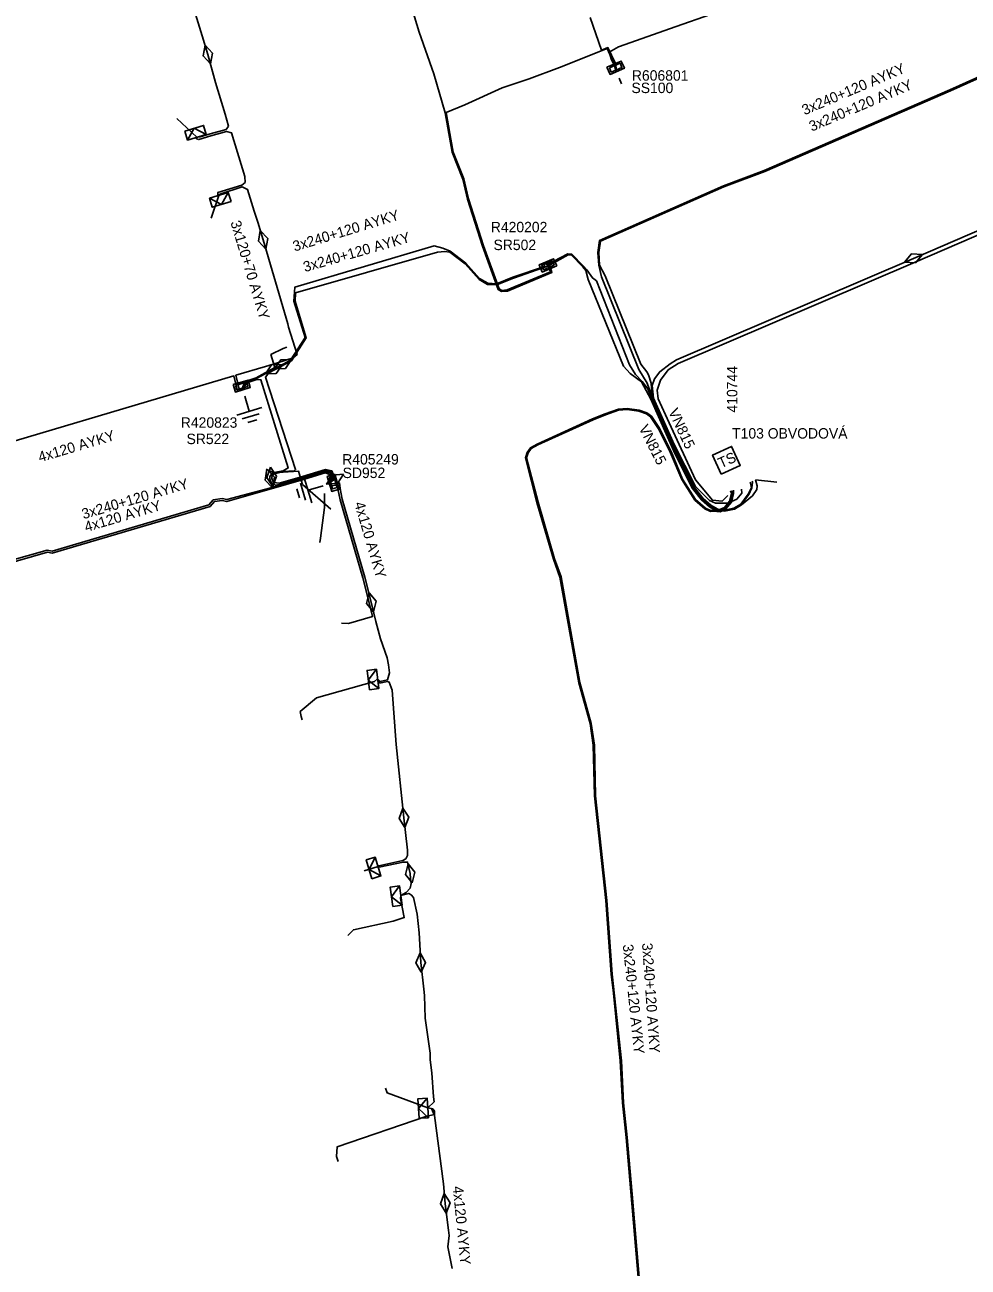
# Model space of a CAD drawing. Extents: x -540028 to -538776, y -1157064 to -1155670.
# Drawn here: x -539683.9 to -539593.4, y -1156179 to -1156059.8 of the extents above; entities that cross this region are included whole.
import ezdxf

# ---------------------------------------------------------------- set-up
doc = ezdxf.new("R2010")
doc.units = 0
for name, color, linetype in [('Vrstva 15', 7, 'Continuous'), ('Vrstva 19', 7, 'Continuous'), ('Vrstva 2', 7, 'Continuous'), ('Vrstva 25', 7, 'Continuous'), ('Vrstva 26', 7, 'Continuous'), ('Vrstva 27', 7, 'Continuous'), ('Vrstva 28', 7, 'Continuous'), ('Vrstva 29', 7, 'Continuous'), ('Vrstva 30', 7, 'Continuous'), ('Vrstva 31', 7, 'Continuous'), ('Vrstva 5', 7, 'Continuous'), ('Vrstva 52', 7, 'Continuous'), ('Vrstva 59', 7, 'Continuous'), ('Vrstva 6', 7, 'Continuous'), ('Vrstva 7', 7, 'Continuous'), ('Vrstva 9', 7, 'Continuous')]:
    doc.layers.add(name, color=color, linetype=linetype)

# ---------------------------------------------------------------- blocks, each defined once
blk = doc.blocks.new('17')
at = {"layer": 'Vrstva 2'}
blk.add_lwpolyline([(-1.875, 0), (0, 0.9375), (1.875, 0), (0, -0.9375)], close=True, dxfattribs=at)
blk = doc.blocks.new('30')
at = {"layer": 'Vrstva 2'}
blk.add_lwpolyline([(-2, 0), (2, 0), (2, 4), (-2, 4)], close=True, dxfattribs=at)
blk.add_text('TS', height=2, dxfattribs=at).set_placement((-1.598, 1))
blk = doc.blocks.new('132')
at = {"layer": 'Vrstva 2'}
for points in [[(-1.5, 1.5), (1.5, 1.5), (1.5, 0), (-1.5, 0)], [(-1.1, 1.2), (1.1, 1.2), (1.1, 0.3), (-1.1, 0.3)]]:
    blk.add_lwpolyline(points, close=True, dxfattribs=at)
blk = doc.blocks.new('23')
at = {"layer": 'Vrstva 2'}
blk.add_lwpolyline([(1.875, -1.8), (-1.875, -1.8), (-1.875, 0), (1.875, 0)], close=True, dxfattribs=at)
blk.add_lwpolyline([(1.875, 0), (0, -1.8), (-1.875, 0)], dxfattribs=at)
blk = doc.blocks.new('11')
at = {"layer": 'Vrstva 2'}
for p, q in [((0, -4.3), (0, -1.3)), ((-2.5, -4.3), (2.5, -4.3)), ((-1.7, -5.3), (1.7, -5.3)), ((-0.9, -6.3), (0.9, -6.3))]:
    blk.add_line(p, q, dxfattribs=at)

msp = doc.modelspace()

# ---------------------------------------------------------------- linework, layer by layer
at = {"layer": 'Vrstva 5'}
for points in [[(-539633.67, -1156082.44), (-539633.35, -1156083.51), (-539637.62, -1156085.3), (-539638.17, -1156085.35), (-539638.49, -1156085.16), (-539640.01, -1156081), (-539641.45, -1156076.48), (-539641.9, -1156074.55), (-539642.92, -1156071.98), (-539643.25, -1156070.19), (-539643.58, -1156068.19), (-539644.69, -1156064.44), (-539646.1, -1156060.45), (-539649.52, -1156049.19), (-539652.59, -1156038.5), (-539653.52, -1156037.39), (-539654.18, -1156037.39), (-539654.73, -1156036.76), (-539661.99, -1156012.49), (-539663.02, -1156008.83), (-539665.83, -1155999.41), (-539668.68, -1155989.83), (-539669.36, -1155987.52), (-539672.43, -1155977.35)], [(-539663.33, -1156094.84), (-539663.67, -1156093.39), (-539660.82, -1156092.54), (-539659.67, -1156092.2), (-539658.19, -1156091.72), (-539657.78, -1156091.38), (-539658.62, -1156088.77), (-539658.68, -1156088.44), (-539660.04, -1156083.86), (-539661.07, -1156080.38), (-539661.57, -1156078.69), (-539661.92, -1156077.65), (-539662.55, -1156075.55), (-539663.08, -1156075.3), (-539665.2, -1156075.99), (-539665.3, -1156076.12), (-539665.4, -1156076.06), (-539665.41, -1156075.85), (-539663.11, -1156075.14), (-539662.77, -1156074.88), (-539662.83, -1156074.32), (-539664.09, -1156070.12), (-539664.56, -1156069.99), (-539666.09, -1156070.41), (-539667.24, -1156070.76), (-539667.44, -1156070.69), (-539667.41, -1156070.54), (-539667.09, -1156070.51), (-539666.15, -1156070.22), (-539664.61, -1156069.81), (-539664.38, -1156069.48), (-539664.7, -1156068.32), (-539665.62, -1156065.27), (-539666.37, -1156062.6), (-539666.92, -1156060.82), (-539669.11, -1156053.62)], [(-539629.68, -1156059.06), (-539628.6, -1156062.19), (-539627.97, -1156061.93), (-539627.29, -1156063.41), (-539627.16, -1156064.04), (-539627.12, -1156064.22)], [(-539627.17, -1156064.24), (-539627.18, -1156064.22), (-539627.39, -1156063.45), (-539628.04, -1156062.01), (-539632.62, -1156063.84), (-539635.52, -1156064.93), (-539638.12, -1156065.79), (-539641.7, -1156067.43), (-539643.48, -1156068.17), (-539643.15, -1156070.17), (-539642.82, -1156071.96), (-539641.8, -1156074.53), (-539641.35, -1156076.46), (-539639.91, -1156080.96), (-539638.41, -1156085.1), (-539638.15, -1156085.25), (-539637.64, -1156085.2), (-539633.48, -1156083.46), (-539633.85, -1156082.51)], [(-539614.32, -1156103.64), (-539614.27, -1156103.74), (-539614.2, -1156104.18), (-539614.5, -1156104.8), (-539615.22, -1156105.74), (-539615.87, -1156106.13), (-539616.79, -1156106.33), (-539617.41, -1156106.25), (-539618.1, -1156105.86), (-539618.84, -1156105.21), (-539619.69, -1156104.13), (-539621.32, -1156100.89), (-539623.11, -1156096.87), (-539623.68, -1156095.59), (-539624.21, -1156094.14), (-539625, -1156092.83), (-539628.57, -1156083.93), (-539628.83, -1156082.82), (-539628.93, -1156081.6), (-539628.79, -1156080.45), (-539616.88, -1156075.19), (-539612.96, -1156073.72), (-539595.14, -1156065.98), (-539590.15, -1156063.74)], [(-539590.11, -1156063.84), (-539595.1, -1156066.08), (-539612.92, -1156073.82), (-539616.84, -1156075.29), (-539628.69, -1156080.51), (-539628.83, -1156081.6), (-539628.78, -1156082.82), (-539628.24, -1156083.84), (-539624.8, -1156092.32), (-539624.25, -1156093.07), (-539624.07, -1156093.33), (-539623.83, -1156094.15), (-539623.73, -1156095.62), (-539621.36, -1156100.91), (-539619.73, -1156104.16), (-539618.88, -1156105.24), (-539618.13, -1156105.9), (-539617.43, -1156106.3), (-539616.79, -1156106.38), (-539615.85, -1156106.18), (-539615.19, -1156105.78), (-539614.46, -1156104.83), (-539614.15, -1156104.2), (-539614.1, -1156103.65), (-539614.14, -1156103.56)], [(-539564.81, -1156067.55), (-539598.65, -1156082.17), (-539621.38, -1156091.91), (-539621.98, -1156092.29), (-539623, -1156093.04), (-539623.5, -1156093.73), (-539623.72, -1156094.37), (-539623.59, -1156095.59), (-539621.62, -1156100.02), (-539619.58, -1156104.07), (-539618.23, -1156105.4), (-539617.64, -1156105.67), (-539616.45, -1156105.66), (-539615.61, -1156105.28), (-539615.13, -1156104.7), (-539615.15, -1156104.32)], [(-539616.45, -1156104.93), (-539617, -1156105.46), (-539617.94, -1156105.36), (-539619.56, -1156103.41), (-539622.1, -1156097.96), (-539623.16, -1156095.64), (-539623.25, -1156094.82), (-539622.92, -1156093.87), (-539622.19, -1156092.87), (-539621.22, -1156092.27), (-539598.49, -1156082.53), (-539564.69, -1156067.93)], [(-539659.15, -1156092.33), (-539658.42, -1156091.92), (-539657.04, -1156089.77), (-539658.1, -1156086.28), (-539658.03, -1156084.94), (-539644.64, -1156080.96), (-539643.82, -1156081.18), (-539643.1, -1156081.46), (-539641.6, -1156082.62), (-539640.28, -1156084.11), (-539639.49, -1156084.56), (-539638.66, -1156084.61), (-539637.08, -1156083.98), (-539634.05, -1156082.96), (-539634.05, -1156082.83), (-539634.16, -1156082.62)], [(-539660.23, -1156103.13), (-539660.14, -1156102.94), (-539659.96, -1156102.83), (-539659.14, -1156102.62), (-539658.08, -1156102.56), (-539657.94, -1156102.43), (-539660.83, -1156093.58), (-539660.5, -1156093.16), (-539658.35, -1156092), (-539656.93, -1156089.79), (-539658, -1156086.26), (-539657.95, -1156085.47), (-539644.31, -1156081.58), (-539643.63, -1156081.51), (-539643.14, -1156081.56), (-539641.66, -1156082.7), (-539640.34, -1156084.19), (-539639.52, -1156084.66), (-539638.64, -1156084.71), (-539637.04, -1156084.08), (-539633.67, -1156082.88), (-539631.8, -1156081.82), (-539631.46, -1156081.87), (-539630.38, -1156082.97), (-539630.08, -1156083.34), (-539629.85, -1156084.18), (-539626.47, -1156092.52), (-539625.85, -1156093.2), (-539624.76, -1156094.03), (-539623.86, -1156095.67), (-539621.5, -1156100.97), (-539620.6, -1156102.81), (-539619.86, -1156104.24), (-539618.99, -1156105.34), (-539618.22, -1156106.02), (-539617.48, -1156106.45), (-539617.21, -1156106.48), (-539616.67, -1156106.24), (-539616.1, -1156105.57), (-539615.92, -1156104.73), (-539615.92, -1156104.4)], [(-539634.03, -1156082.59), (-539633.83, -1156082.8), (-539631.82, -1156081.72), (-539631.42, -1156081.77), (-539630.3, -1156082.91), (-539630, -1156083.28), (-539629.46, -1156084.04), (-539629.06, -1156084.33), (-539625.89, -1156092.39), (-539625.31, -1156093.31), (-539624.68, -1156093.97), (-539624.14, -1156094.67), (-539623.77, -1156095.64), (-539623.21, -1156096.91), (-539621.41, -1156100.93), (-539620.53, -1156102.76), (-539619.78, -1156104.18), (-539618.92, -1156105.28), (-539618.16, -1156105.94), (-539617.45, -1156106.35), (-539616.79, -1156106.43), (-539615.83, -1156106.23), (-539615.16, -1156105.82), (-539614.1, -1156104.97), (-539613.67, -1156104.34), (-539613.64, -1156103.99), (-539613.81, -1156103.41)], [(-539659.14, -1156090.81), (-539660.32, -1156091.4), (-539659.94, -1156092.65), (-539661.72, -1156093.62), (-539662.79, -1156093.98), (-539663.14, -1156094.79)], [(-539663.05, -1156094.77), (-539662.77, -1156094.05), (-539661.7, -1156093.7), (-539660.02, -1156092.79)], [(-539660.02, -1156092.79), (-539659.15, -1156092.33)], [(-539693.18, -1156102.14), (-539663.87, -1156093.45), (-539663.52, -1156094.89)], [(-539662.92, -1156094.73), (-539662.73, -1156094.15), (-539661.66, -1156093.8), (-539661.28, -1156093.82), (-539658.65, -1156102.27), (-539659.15, -1156102.57), (-539660.02, -1156102.72), (-539660.27, -1156102.87), (-539660.41, -1156103.09), (-539660.42, -1156103.3)], [(-539616.19, -1156104.47), (-539616.12, -1156104.7), (-539616.29, -1156105.48), (-539616.79, -1156106.08), (-539617.4, -1156106.34), (-539618.11, -1156106.35), (-539618.61, -1156106.13), (-539619.56, -1156105.3), (-539620.8, -1156103.36), (-539621.9, -1156100.71), (-539623.03, -1156098.47), (-539623.79, -1156097.3), (-539624.24, -1156097), (-539624.97, -1156096.73), (-539626.13, -1156096.58), (-539626.97, -1156096.64), (-539628.25, -1156097.09), (-539629.44, -1156097.57), (-539634.75, -1156099.99), (-539635.41, -1156100.34), (-539635.72, -1156100.8), (-539635.87, -1156101.31), (-539634.78, -1156105.58), (-539633.2, -1156111.02), (-539632.57, -1156112.76), (-539630.77, -1156122.89), (-539629.68, -1156126.82), (-539629.37, -1156128.9), (-539629.25, -1156133.75), (-539628.16, -1156143.78), (-539627.65, -1156150.86), (-539627.45, -1156152.68), (-539626.78, -1156159.18), (-539626.56, -1156163.21), (-539626.21, -1156166.54), (-539625.08, -1156179.95)], [(-539616.06, -1156104.46), (-539616.02, -1156104.72), (-539616.19, -1156105.52), (-539616.73, -1156106.16), (-539617.38, -1156106.44), (-539618.13, -1156106.45), (-539618.67, -1156106.21), (-539619.64, -1156105.36), (-539620.89, -1156103.4), (-539621.98, -1156100.75), (-539623.11, -1156098.52), (-539623.87, -1156097.38), (-539624.28, -1156097.08), (-539624.99, -1156096.83), (-539626.13, -1156096.68), (-539626.95, -1156096.74), (-539628.21, -1156097.19), (-539629.4, -1156097.67), (-539634.71, -1156100.07), (-539635.33, -1156100.42), (-539635.62, -1156100.84), (-539635.77, -1156101.31), (-539634.68, -1156105.56), (-539633.1, -1156110.99), (-539632.47, -1156112.74), (-539630.67, -1156122.87), (-539629.58, -1156126.8), (-539629.27, -1156128.9), (-539629.15, -1156133.75), (-539628.06, -1156143.78), (-539627.55, -1156150.85), (-539626.68, -1156159.18), (-539626.46, -1156163.21), (-539626.11, -1156166.53), (-539625.64, -1156171.99), (-539624.98, -1156179.93)], [(-539654.73, -1156103.7), (-539654.16, -1156103.36), (-539654.47, -1156102.54), (-539655.06, -1156102.43), (-539657.27, -1156103.09), (-539659.52, -1156103.75), (-539660.03, -1156103.69), (-539660.14, -1156103.54), (-539660.21, -1156103.3), (-539660.23, -1156103.13)], [(-539687.59, -1156111.81), (-539681.78, -1156110.17), (-539681.32, -1156110.25), (-539666.27, -1156105.81), (-539665.84, -1156105.33), (-539665, -1156105.21), (-539664.55, -1156105.3), (-539660.31, -1156104.19), (-539657.21, -1156103.28), (-539655.07, -1156102.64), (-539654.65, -1156102.74), (-539654.42, -1156103.28), (-539654.79, -1156103.5)], [(-539654.82, -1156103.4), (-539654.56, -1156103.24), (-539654.76, -1156102.87), (-539655.1, -1156102.75), (-539657.18, -1156103.38), (-539660.28, -1156104.29), (-539664.55, -1156105.5), (-539665, -1156105.41), (-539665.74, -1156105.51), (-539666.15, -1156105.99), (-539681.3, -1156110.45), (-539681.77, -1156110.37), (-539687.53, -1156112.01)], [(-539660.42, -1156103.3), (-539660.35, -1156103.55), (-539660.13, -1156103.88), (-539659.75, -1156103.92), (-539657.24, -1156103.18), (-539655.07, -1156102.53), (-539654.57, -1156102.66), (-539654.29, -1156103.32), (-539654.76, -1156103.6)], [(-539642.93, -1156179.1), (-539643.33, -1156177.03), (-539643.21, -1156175.94), (-539643.28, -1156175.44), (-539643.44, -1156174.18), (-539643.58, -1156172.86), (-539643.74, -1156170.97), (-539644.62, -1156164.44), (-539644.89, -1156163.77), (-539645.25, -1156163.7), (-539644.65, -1156163.1), (-539644.71, -1156162.64), (-539644.88, -1156160.34), (-539645.04, -1156159.1), (-539645.03, -1156158.44), (-539645.5, -1156155.07), (-539645.57, -1156152.9), (-539645.65, -1156152.29), (-539645.94, -1156149.75), (-539646.07, -1156146.88), (-539646.29, -1156145.12), (-539646.62, -1156143.49), (-539646.86, -1156143.25), (-539647.09, -1156143.12), (-539647.32, -1156143.17), (-539647.85, -1156143.32), (-539647.34, -1156143.02), (-539646.95, -1156142.62), (-539646.85, -1156142.17), (-539646.91, -1156141.69), (-539646.95, -1156141.19), (-539647.19, -1156140.11), (-539647.63, -1156140.11), (-539649.93, -1156140.58), (-539650.03, -1156140.54), (-539649.96, -1156140.46), (-539647.64, -1156139.95), (-539647.35, -1156139.78), (-539647.19, -1156139.47), (-539647.21, -1156138.97), (-539647.55, -1156135.86), (-539648.3, -1156128.81), (-539648.69, -1156123.6), (-539648.96, -1156122.83), (-539649.11, -1156122.78), (-539649.89, -1156122.92), (-539650.08, -1156122.53), (-539649.82, -1156122.79), (-539649.12, -1156122.6), (-539648.94, -1156121.93), (-539649.04, -1156121.16), (-539649.17, -1156120.49), (-539649.81, -1156118.69), (-539650.23, -1156117), (-539650.44, -1156116.21), (-539650.68, -1156115.17), (-539651.29, -1156112.77), (-539653.49, -1156105.29), (-539653.68, -1156104.26), (-539653.74, -1156103.72), (-539654.69, -1156103.82)]]:
    msp.add_lwpolyline(points, dxfattribs=at)
at = {"layer": 'Vrstva 52'}
for points in [[(-539627.08, -1156064.21), (-539627.65, -1156063.01), (-539627.84, -1156062.39), (-539626.96, -1156061.87), (-539621.43, -1156059.92), (-539618.13, -1156058.76), (-539610.74, -1156057.78), (-539607.21, -1156057.16), (-539606.29, -1156057.07)], [(-539655.17, -1156104.74), (-539655.17, -1156106.08), (-539655.57, -1156109.01), (-539655.62, -1156109.44)], [(-539654.67, -1156104.01), (-539653.92, -1156103.94), (-539653.88, -1156104.29), (-539653.68, -1156105.34), (-539651.48, -1156112.82), (-539650.87, -1156115.22), (-539650.56, -1156116.53), (-539652.87, -1156117.21), (-539653.53, -1156117.18)], [(-539650.08, -1156122.53), (-539650.37, -1156122.76), (-539655.93, -1156124.33), (-539657.52, -1156125.66), (-539657.41, -1156126.14), (-539657.32, -1156126.45)], [(-539647.85, -1156143.32), (-539647.89, -1156143.6), (-539647.51, -1156145.43), (-539648.59, -1156145.78), (-539652.4, -1156146.6), (-539652.94, -1156147.14)], [(-539645.25, -1156163.7), (-539649.15, -1156162.26), (-539649.33, -1156161.81)], [(-539645.25, -1156163.7), (-539644.78, -1156163.8), (-539644.62, -1156164.02), (-539644.6, -1156164.34), (-539645.35, -1156164.5), (-539653.96, -1156167.45), (-539654.02, -1156168.37), (-539653.86, -1156168.85)]]:
    msp.add_lwpolyline(points, dxfattribs=at)
at = {"layer": 'Vrstva 59'}
for points in [[(-539626.89, -1156064.88), (-539626.68, -1156065.42)], [(-539667.41, -1156070.54), (-539669.34, -1156068.75)], [(-539665.3, -1156076.12), (-539666.05, -1156078.32)], [(-539659.14, -1156090.81), (-539658.8, -1156090.7)], [(-539613.81, -1156103.41), (-539611.75, -1156103.64)], [(-539650.03, -1156140.54), (-539651.37, -1156140.95)]]:
    msp.add_lwpolyline(points, dxfattribs=at)
at = {"layer": 'Vrstva 9'}
msp.add_lwpolyline([(-539660.77, -1156102.39), (-539660.08, -1156102.76), (-539659.14, -1156102.67), (-539657.67, -1156102.58), (-539657.29, -1156103.86), (-539654.56, -1156106.22)], dxfattribs=at)

# ---------------------------------------------------------------- block references
at = {"layer": 'Vrstva 15', "xscale": 0.5, "yscale": 0.5}
for p, rotation in [((-539663.01, -1156094.78), 16.776063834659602), ((-539654.69, -1156103.81), -73.47012781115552)]:
    msp.add_blockref('11', p, dxfattribs=dict(at, rotation=rotation))
at = {"layer": 'Vrstva 19'}
for p, xscale, yscale, rotation in [((-539666.37, -1156062.6), 0.5, 0.5, -74.31000705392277), ((-539661.07, -1156080.38), 0.5, 0.5, 106.48127223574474), ((-539598.65, -1156082.17), 0.49999999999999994, 0.5000000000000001, 23.36289457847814), ((-539659.15, -1156092.33), 0.5, 0.5, -151.56646189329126), ((-539660.02, -1156092.79), 0.5, 0.5, 28.433538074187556), ((-539660.42, -1156103.3), 0.49999999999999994, 0.5000000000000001, -73.15427219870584), ((-539660.24, -1156103.13), 0.5, 0.5, -82.29500280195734), ((-539654.16, -1156103.36), 0.49999999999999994, 0.5, -149.0934408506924), ((-539650.68, -1156115.17), 0.5000000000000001, 0.5, -77.00538325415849), ((-539647.55, -1156135.86), 0.5, 0.5000000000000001, -83.76093023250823), ((-539646.95, -1156141.19), 0.5, 0.5, 102.52880772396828), ((-539645.94, -1156149.75), 0.5, 0.49999999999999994, 92.59350639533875), ((-539643.58, -1156172.86), 0.5000000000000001, 0.4999999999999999, -83.94580809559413)]:
    msp.add_blockref('17', p, dxfattribs=dict(at, xscale=xscale, yscale=yscale, rotation=rotation))
at = {"layer": 'Vrstva 25', "xscale": 0.5, "yscale": 0.5, "rotation": 24.52268064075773}
msp.add_blockref('30', (-539616.18, -1156102.45), dxfattribs=at)
at = {"layer": 'Vrstva 28'}
for p, xscale, yscale, rotation in [((-539627.08, -1156064.21), 0.5, 0.5, 23.155085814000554), ((-539633.87, -1156082.49), 0.49999999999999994, 0.5000000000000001, -156.84803046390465), ((-539663.01, -1156094.78), 0.5, 0.49999999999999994, 16.99999998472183), ((-539654.69, -1156103.81), 0.5, 0.5, -73.47012781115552)]:
    msp.add_blockref('132', p, dxfattribs=dict(at, xscale=xscale, yscale=yscale, rotation=rotation))
at = {"layer": 'Vrstva 31'}
for p, xscale, yscale, rotation in [((-539667.41, -1156070.54), 0.5, 0.5, -163.2030833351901), ((-539665.3, -1156076.12), 0.5, 0.5, 16.796916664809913), ((-539650.08, -1156122.53), 0.49999999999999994, 0.5, -83.06008055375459), ((-539650.03, -1156140.54), 0.5, 0.49999999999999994, -73.0673777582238), ((-539647.85, -1156143.31), 0.5000000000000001, 0.5, -82.37356384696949), ((-539645.25, -1156163.7), 0.5, 0.49999999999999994, -86.32077252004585)]:
    msp.add_blockref('23', p, dxfattribs=dict(at, xscale=xscale, yscale=yscale, rotation=rotation))

# ---------------------------------------------------------------- texts
at = {"layer": 'Vrstva 26'}
msp.add_text('410744', height=1, rotation=90, dxfattribs=at).set_placement((-539615.55, -1156096.96))
at = {"layer": 'Vrstva 27'}
msp.add_text('T103 OBVODOVÁ', height=1, dxfattribs=at).set_placement((-539616.05, -1156099.46))
at = {"layer": 'Vrstva 29'}
for s, p in [('R606801', (-539625.67, -1156065.11)), ('R420202', (-539639.21, -1156079.66)), ('R420823', (-539668.96, -1156098.42))]:
    msp.add_text(s, height=1, dxfattribs=at).set_placement(p)
msp.add_text('R405249', height=1, rotation=0.046, dxfattribs=at).set_placement((-539653.47, -1156101.95))
at = {"layer": 'Vrstva 30'}
msp.add_text('SS100', height=1, dxfattribs=at).set_placement((-539625.71, -1156066.3))
for s, rotation, p in [('SR502', 359.947, (-539638.95, -1156081.37)), ('SR522', 359.969, (-539668.41, -1156099.99)), ('SD952', 0.046, (-539653.43, -1156103.25))]:
    msp.add_text(s, height=1, rotation=rotation, dxfattribs=at).set_placement(p)
at = {"layer": 'Vrstva 6'}
for s, rotation, p in [('3x240+120 AYKY', 23, (-539609.1, -1156068.44)), ('3x240+120 AYKY', 23, (-539608.41, -1156070.01)), ('3x120+70 AYKY', 286.803, (-539664.21, -1156078.7)), ('3x240+120 AYKY', 17, (-539658.04, -1156081.52)), ('3x240+120 AYKY', 16, (-539657.05, -1156083.49)), ('4x120 AYKY', 16.516, (-539682.48, -1156101.74)), ('3x240+120 AYKY', 16.419, (-539678.3, -1156107.21)), ('4x120 AYKY', 16.421, (-539678.04, -1156108.44)), ('4x120 AYKY', 286.41, (-539652.32, -1156105.68)), ('3x240+120 AYKY', 276, (-539626.55, -1156148.04)), ('3x240+120 AYKY', 274, (-539624.7, -1156147.9)), ('4x120 AYKY', 275.711, (-539642.87, -1156171.25))]:
    msp.add_text(s, height=1, rotation=rotation, dxfattribs=at).set_placement(p)
at = {"layer": 'Vrstva 7'}
for rotation, p in [(294.988, (-539622.2, -1156096.85)), (296.735, (-539625.04, -1156098.44))]:
    msp.add_text('VN815', height=1, rotation=rotation, dxfattribs=at).set_placement(p)

doc.saveas('drawing.dxf')
